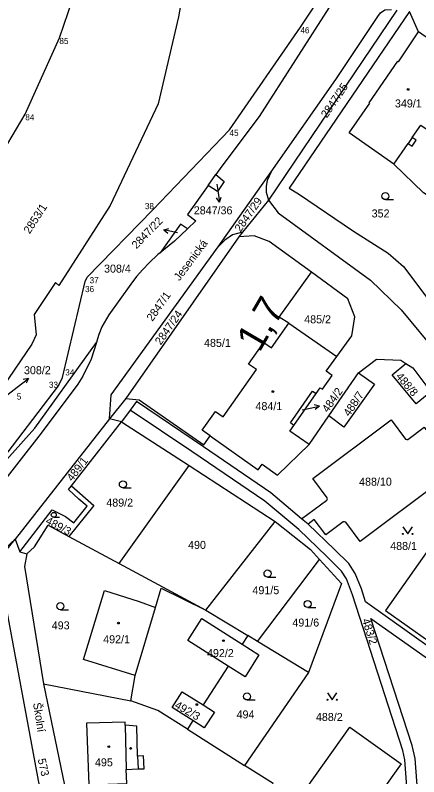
# Model space of a CAD drawing. Extents: x -558358 to -557517, y -1073785 to -1073189.
# Drawn here: x -558075.9 to -557990.2, y -1073433.6 to -1073271.9 of the extents above; entities that cross this region are included whole.
import ezdxf

# ---------------------------------------------------------------- set-up
doc = ezdxf.new("R2010")
doc.units = 0
for name, color, linetype in [('Hranice parcel', 7, 'Continuous'), ('Návěst místo trati', 7, 'Continuous'), ('Parcelní čísla', 7, 'Continuous'), ('Pop  PČ popisy', 7, 'Continuous'), ('Svazek obcí údolí Desné', 7, 'Continuous'), ('Vnitřní kresba', 7, 'Continuous'), ('Vrstva 60', 7, 'Continuous'), ('Značky budov', 7, 'Continuous'), ('Značky kultur', 7, 'Continuous')]:
    doc.layers.add(name, color=color, linetype=linetype)

msp = doc.modelspace()

# ---------------------------------------------------------------- linework, layer by layer
at = {"layer": 'Hranice parcel'}
for p, q in [((-557994.86, -1073270.9), (-558022.09, -1073311.21)), ((-557990.25, -1073275.48), (-557992.18, -1073271.14)), ((-558032.81, -1073321.13), (-558021.55, -1073305.19)), ((-558034.93, -1073308.06), (-558033.31, -1073305.78)), ((-558033.31, -1073305.78), (-558031.49, -1073307.27)), ((-558032.97, -1073309.39), (-558034.93, -1073308.06)), ((-558031.49, -1073307.27), (-558032.97, -1073309.39)), ((-558022.59, -1073309.53), (-558022.09, -1073311.21)), ((-558022.09, -1073311.21), (-558027.65, -1073318.03)), ((-558037.52, -1073315.57), (-558039.34, -1073317.31)), ((-558039.34, -1073317.31), (-558042.1, -1073319.93)), ((-558027.65, -1073318.03), (-558029.72, -1073318.58)), ((-558027.65, -1073318.03), (-558028.41, -1073318.97)), ((-558028.41, -1073318.97), (-558052.39, -1073353.27)), ((-558042.1, -1073319.93), (-558045.13, -1073322.4)), ((-558045.13, -1073322.4), (-558045.59, -1073322.77)), ((-558017.77, -1073337.32), (-558007.59, -1073344.4)), ((-558058.43, -1073340.61), (-558058.64, -1073341.4)), ((-558058.64, -1073341.4), (-558059.76, -1073344.95)), ((-558009.3, -1073357), (-558003.01, -1073347.89)), ((-558003.01, -1073347.89), (-557999.59, -1073350.23)), ((-557999.59, -1073350.23), (-558006.08, -1073359.37)), ((-558016.74, -1073359.04), (-558011.99, -1073352.26)), ((-558055.85, -1073357.6), (-558055.56, -1073352.56)), ((-558052.39, -1073353.27), (-558055.85, -1073357.6)), ((-558051.46, -1073355.75), (-558053.32, -1073358.25)), ((-558013.44, -1073363.06), (-558009.3, -1073357)), ((-558006.08, -1073359.37), (-558009.3, -1073357)), ((-558055.85, -1073357.6), (-558075.89, -1073383.19)), ((-558063.99, -1073371.84), (-558053.32, -1073358.25)), ((-558053.32, -1073358.25), (-558055.85, -1073357.6)), ((-558053.32, -1073358.25), (-558038.99, -1073367.55)), ((-558053.86, -1073388.3), (-558038.99, -1073367.55)), ((-558038.99, -1073367.55), (-558020.67, -1073379.44)), ((-558035.4, -1073398.23), (-558020.67, -1073379.44)), ((-558075.89, -1073383.19), (-558086.19, -1073392.25)), ((-558081, -1073389.4), (-558075.89, -1073383.19)), ((-558075.89, -1073383.19), (-558074.9, -1073385.82)), ((-558064.49, -1073382.58), (-558053.86, -1073388.3)), ((-558074.9, -1073385.82), (-558073.48, -1073386.28)), ((-558024.42, -1073404.91), (-558011.29, -1073387.48)), ((-558053.86, -1073388.3), (-558035.4, -1073398.23)), ((-558068.26, -1073448.76), (-558079.07, -1073390.9)), ((-558035.4, -1073398.23), (-558026.52, -1073403.63)), ((-558039.27, -1073404.7), (-558036.29, -1073400)), ((-558036.29, -1073400), (-558027.69, -1073405.45)), ((-558026.52, -1073403.63), (-558027.69, -1073405.45)), ((-558024.42, -1073404.91), (-558026.52, -1073403.63)), ((-558030.69, -1073410.09), (-558039.27, -1073404.7)), ((-558027.69, -1073405.45), (-558024.15, -1073407.69)), ((-558013.61, -1073411.49), (-558024.42, -1073404.91)), ((-558024.15, -1073407.69), (-558027.08, -1073412.36)), ((-558030.69, -1073410.09), (-558036.02, -1073418.35)), ((-558027.08, -1073412.36), (-558030.69, -1073410.09)), ((-558013.61, -1073411.49), (-558027.22, -1073431.17)), ((-558069.9, -1073413.89), (-558063.79, -1073443.12)), ((-558069.9, -1073413.89), (-558051.38, -1073417.49)), ((-558042.56, -1073418.87), (-558040.48, -1073415.56)), ((-558040.48, -1073415.56), (-558036.02, -1073418.35)), ((-558036.02, -1073418.35), (-558033.6, -1073419.86)), ((-558038.16, -1073421.67), (-558042.56, -1073418.87)), ((-558033.6, -1073419.86), (-558035.74, -1073423.21)), ((-558038.16, -1073421.67), (-558039.34, -1073423.5)), ((-558035.74, -1073423.21), (-558038.16, -1073421.67)), ((-558039.34, -1073423.5), (-558027.22, -1073431.17))]:
    msp.add_line(p, q, dxfattribs=at)
for points in [[(-557998.11, -1073217.81), (-557996.7, -1073222.28), (-557998.38, -1073242.39), (-558002.78, -1073257.43), (-558008.62, -1073269.37), (-558024.06, -1073293.44), (-558032.02, -1073303.96), (-558033.31, -1073305.78)], [(-558021.55, -1073305.19), (-558007.79, -1073285.56), (-557998.91, -1073272.25), (-557998.29, -1073271.45), (-557997.41, -1073270.82), (-557995.96, -1073270.7)], [(-557992.18, -1073271.14), (-558017.7, -1073308.66), (-558015.75, -1073309.85), (-558004.08, -1073317.8), (-557996.67, -1073322.48), (-557993.43, -1073325.31), (-557988.49, -1073331.84)], [(-557995.47, -1073303.55), (-558004.99, -1073296.92), (-558000.61, -1073290.62), (-558000.75, -1073290.52), (-557994.62, -1073281.73), (-557994.47, -1073281.84), (-557990.25, -1073275.48)], [(-557995.47, -1073303.55), (-557992.42, -1073299.14), (-557991.6, -1073299.71), (-557990.74, -1073298.46), (-557991.57, -1073297.9), (-557989.74, -1073295.26), (-557987.45, -1073296.82), (-557987.09, -1073296.7), (-557984.08, -1073292.32), (-557984.13, -1073291.92), (-557983.12, -1073290.42), (-557984.28, -1073289.64), (-557980.42, -1073284.02), (-557980.45, -1073282.32), (-557980.68, -1073282.11), (-557990.25, -1073275.48)], [(-557977.43, -1073317.43), (-557989.2, -1073309.62), (-557995.47, -1073303.55)], [(-558021.55, -1073305.19), (-558022.41, -1073307.04), (-558022.62, -1073308.24), (-558022.59, -1073309.53)], [(-558034.93, -1073308.06), (-558039.34, -1073314.26), (-558037.52, -1073315.57)], [(-558022.09, -1073311.21), (-558020.08, -1073313.87), (-558000.41, -1073328.2), (-557993.92, -1073334.5), (-557986.04, -1073343.93), (-557967.1, -1073369.2), (-557918.24, -1073434.51), (-557914.64, -1073436.24), (-557909.55, -1073436.22), (-557905.05, -1073434.1), (-557902.57, -1073430.65), (-557891.22, -1073414.37), (-557877.97, -1073395.43)], [(-558039.34, -1073317.31), (-558040.78, -1073316.28), (-558045.13, -1073322.4)], [(-558029.72, -1073318.58), (-558031.41, -1073319.68), (-558032.81, -1073321.13)], [(-558012.98, -1073326.49), (-558021.93, -1073320.01), (-558025.13, -1073318.78), (-558028.41, -1073318.97)], [(-558055.56, -1073352.56), (-558041.67, -1073333.36), (-558032.81, -1073321.13)], [(-558045.59, -1073322.77), (-558047.44, -1073324.48), (-558048.82, -1073325.91), (-558050.13, -1073327.44), (-558051.32, -1073329.04), (-558056.02, -1073335.51), (-558057.5, -1073338.08), (-558058.16, -1073339.69), (-558058.43, -1073340.61)], [(-558017.77, -1073337.32), (-558019.82, -1073336.05), (-558012.98, -1073326.49)], [(-558007.59, -1073344.4), (-558004.4, -1073339.98), (-558003.75, -1073335.95), (-558005.22, -1073332.12), (-558012.98, -1073326.49)], [(-558034.47, -1073361.24), (-558036.19, -1073360.05), (-558033.38, -1073356.04), (-558031.73, -1073357.2), (-558024.67, -1073347.17), (-558026.34, -1073346.01), (-558023.11, -1073341.4), (-558021.44, -1073342.56), (-558017.77, -1073337.32)], [(-558083.8, -1073372.96), (-558071.77, -1073359.59), (-558059.92, -1073343.2), (-558058.64, -1073341.4)], [(-558011.99, -1073352.26), (-558011.14, -1073351.05), (-558010.65, -1073351.33), (-558008.6, -1073348.45), (-558009.82, -1073347.53), (-558007.59, -1073344.4)], [(-558059.76, -1073344.95), (-558061.55, -1073348.53), (-558062.6, -1073350.23), (-558070.37, -1073360.66), (-558089.91, -1073385.65), (-558114.04, -1073415.6), (-558119.93, -1073422.75), (-558120.74, -1073423.38), (-558121.71, -1073423.79), (-558122.74, -1073423.86)], [(-558003.01, -1073347.89), (-557999.15, -1073344.94), (-557994.02, -1073345.2), (-557992.92, -1073345.89)], [(-557987.64, -1073351.9), (-557990.77, -1073354.47), (-557995.82, -1073348.28), (-557992.92, -1073345.89)], [(-557992.92, -1073345.89), (-557991.47, -1073346.8), (-557987.64, -1073351.9)], [(-558016.74, -1073359.04), (-558017.42, -1073358.44), (-558012.76, -1073351.73), (-558011.99, -1073352.26)], [(-558052.39, -1073353.27), (-558049.55, -1073353.62), (-558035.82, -1073363.11), (-558034.47, -1073361.24)], [(-558015.07, -1073378.83), (-558021.62, -1073373.3), (-558035.88, -1073363.58), (-558050.18, -1073353.97), (-558051.46, -1073355.75)], [(-557997.16, -1073446.28), (-557996.18, -1073446.14), (-557992.37, -1073440.37), (-557993.13, -1073429.99), (-557993.58, -1073428.02), (-558004.25, -1073395), (-558005.55, -1073391.58), (-558006.57, -1073389.94), (-558009.69, -1073386.81), (-558015.69, -1073381.13), (-558022.86, -1073375.1), (-558038.38, -1073364.54), (-558051.46, -1073355.75)], [(-558015.07, -1073378.83), (-558009.7, -1073374.87), (-558009.55, -1073374.62), (-558009.63, -1073374.36), (-558012.72, -1073370.26), (-557996.07, -1073357.8), (-557992.97, -1073361.92), (-557992.74, -1073362.04), (-557992.48, -1073361.98), (-557989.05, -1073359.38), (-557985.61, -1073364.04), (-557988.36, -1073366.15), (-557988.52, -1073366.38), (-557988.48, -1073366.66), (-557985.4, -1073370.76), (-558002.63, -1073383.68), (-558005.71, -1073379.56), (-558005.98, -1073379.48), (-558006.26, -1073379.51), (-558009.96, -1073382.24), (-558012.37, -1073378.99), (-558013.71, -1073380.01)], [(-558013.44, -1073363.06), (-558017.55, -1073360.24), (-558016.74, -1073359.04)], [(-558034.47, -1073361.24), (-558024.32, -1073368.43), (-558023.47, -1073367.24), (-558020.17, -1073369.56), (-558013.44, -1073363.06)], [(-558074.9, -1073385.82), (-558068.06, -1073376.95), (-558065.25, -1073378.32), (-558063.46, -1073379.72), (-558060.6, -1073376.18), (-558062.42, -1073374.7), (-558064.61, -1073372.63), (-558063.99, -1073371.84)], [(-558063.99, -1073371.84), (-558059.19, -1073376.03), (-558064.49, -1073382.58)], [(-557973.25, -1073383.95), (-557982.53, -1073377.43), (-557997.25, -1073398.28), (-557988.03, -1073404.82), (-557981.86, -1073396.11), (-557980.74, -1073396.9), (-557978.29, -1073393.44), (-557979.41, -1073392.65), (-557973.25, -1073383.95)], [(-558020.67, -1073379.44), (-558013.21, -1073385.39), (-558011.29, -1073387.48)], [(-558013.71, -1073380.01), (-558014.05, -1073379.69), (-558015.07, -1073378.83)], [(-558073.48, -1073386.28), (-558071.82, -1073384.76), (-558068.89, -1073380.22), (-558064.49, -1073382.58)], [(-557986.61, -1073406.29), (-557987.5, -1073406.44), (-558001.47, -1073396.48), (-558002.38, -1073393.7), (-558003.7, -1073390.42), (-558005.05, -1073388.34), (-558008.08, -1073385.35), (-558013.71, -1073380.01)], [(-558073.48, -1073386.28), (-558073.96, -1073388.93), (-558069.9, -1073413.89)], [(-558011.29, -1073387.48), (-558006.6, -1073392.58), (-558013.61, -1073411.49)], [(-558051.38, -1073417.49), (-558050.42, -1073412.09), (-558061.44, -1073408.67), (-558056.95, -1073394.08), (-558049.56, -1073396.36), (-558046.09, -1073397.7), (-558044.91, -1073393.54), (-558035.4, -1073398.23)], [(-557990.11, -1073441.11), (-557990.95, -1073429.72), (-557991.6, -1073426.99), (-558000.34, -1073399.97), (-557986.42, -1073409.86), (-557979.13, -1073399.38), (-557977.23, -1073400.7), (-557975.75, -1073398.59), (-557966.19, -1073404.96)], [(-558039.34, -1073423.5), (-558045.61, -1073419.54), (-558051.38, -1073417.49)], [(-558049.8, -1073431.93), (-558048.54, -1073431.88), (-558048.64, -1073429.15), (-558049.91, -1073429.2), (-558050.08, -1073422.86), (-558052.56, -1073422.66), (-558052.57, -1073422.02), (-558060.76, -1073422.24), (-558060.26, -1073435.32), (-558052.21, -1073435.02), (-558052.32, -1073432.02), (-558049.8, -1073431.93)], [(-558023.22, -1073448.98), (-558004.82, -1073423.06), (-557993.94, -1073430.83), (-558002.36, -1073442.69), (-558001.05, -1073443.62)], [(-558024.27, -1073448.53), (-558022.77, -1073438.58), (-558021.1, -1073435.02), (-558027.22, -1073431.17)]]:
    msp.add_lwpolyline(points, dxfattribs=at)
at = {"layer": 'Pop  PČ popisy'}
for p, q in [((-558033.09, -1073307.84), (-558032.96, -1073308.65)), ((-558032.96, -1073308.65), (-558032.49, -1073311.61)), ((-558032.49, -1073311.61), (-558033.14, -1073310.7)), ((-558032.49, -1073311.61), (-558032.15, -1073310.55)), ((-558044.37, -1073317.47), (-558043.29, -1073317.2)), ((-558041.45, -1073318.14), (-558044.37, -1073317.47)), ((-558044.37, -1073317.47), (-558043.51, -1073318.18)), ((-558075.47, -1073350.88), (-558073.1, -1073349.03)), ((-558073.1, -1073349.03), (-558074.2, -1073349.25)), ((-558073.1, -1073349.03), (-558073.59, -1073350.04)), ((-558078.72, -1073353.4), (-558075.47, -1073350.88)), ((-558014.95, -1073355.7), (-558014.23, -1073355.56)), ((-558014.23, -1073355.56), (-558011.3, -1073354.94)), ((-558011.3, -1073354.94), (-558012.38, -1073354.65)), ((-558011.3, -1073354.94), (-558012.17, -1073355.63))]:
    msp.add_line(p, q, dxfattribs=at)
at = {"layer": 'Svazek obcí údolí Desné'}
msp.add_line((-558083.8, -1073372.96), (-558066.74, -1073350.64), dxfattribs=at)
for points in [[(-558082.18, -1073306.93), (-558073.77, -1073292.96), (-558066.53, -1073276.76), (-558060.05, -1073257.85), (-558056.4, -1073244.89), (-558045.6, -1073201.5), (-558043.07, -1073189.63)], [(-558025.59, -1073189.61), (-558032.09, -1073212.63), (-558035.15, -1073249.33), (-558039.97, -1073265.01), (-558041.24, -1073272.26), (-558045.55, -1073290.79), (-558055.77, -1073312.33), (-558066.64, -1073329.29), (-558067.37, -1073328.67), (-558071.91, -1073335.47), (-558071.45, -1073339.78), (-558072.38, -1073341.74), (-558078.52, -1073350.81)], [(-558066.74, -1073350.64), (-558065.9, -1073348.86), (-558061.08, -1073328.44), (-558060.65, -1073327.54), (-558046.7, -1073313.29), (-558030.4, -1073296.27), (-558015.33, -1073274.48), (-558010.02, -1073266.4), (-558006.82, -1073259.79), (-558003.58, -1073251.39), (-558001.93, -1073245.63), (-558000.3, -1073233.47), (-558000.14, -1073230.76), (-558000.21, -1073228.76), (-558000.67, -1073225.31), (-558001.93, -1073222.03), (-558003.18, -1073219.55), (-558003.41, -1073218.32), (-558003.28, -1073217.31), (-558002.8, -1073216.38), (-558000.9, -1073214.81), (-557999.34, -1073213.91), (-558005.3, -1073194.99), (-558007.29, -1073189.83)]]:
    msp.add_lwpolyline(points, dxfattribs=at)
at = {"layer": 'Vnitřní kresba'}
for p, q in [((-557991.57, -1073297.9), (-557992.42, -1073299.14)), ((-558050.42, -1073412.09), (-558046.09, -1073397.7)), ((-558052.56, -1073422.66), (-558052.32, -1073432.02)), ((-558049.91, -1073429.2), (-558049.8, -1073431.93))]:
    msp.add_line(p, q, dxfattribs=at)
at = {"layer": 'Vrstva 60'}
for p, q in [((-558015.33, -1073274.48), (-558015.33, -1073274.48)), ((-558066.53, -1073276.76), (-558066.53, -1073276.76)), ((-558073.77, -1073292.96), (-558073.77, -1073292.96)), ((-558030.4, -1073296.27), (-558030.4, -1073296.27)), ((-558046.7, -1073313.29), (-558046.7, -1073313.29)), ((-558060.65, -1073327.54), (-558060.65, -1073327.54)), ((-558061.08, -1073328.44), (-558061.08, -1073328.44)), ((-558065.9, -1073348.86), (-558065.9, -1073348.86)), ((-558066.74, -1073350.64), (-558066.74, -1073350.64))]:
    msp.add_line(p, q, dxfattribs=at)
at = {"layer": 'Značky budov'}
for centre in [(-557992.44, -1073287.7), (-558021.18, -1073351.82), (-558053.98, -1073400.98), (-558031.67, -1073404.71), (-558037.33, -1073418.27), (-558056.04, -1073427.22), (-558051.4, -1073427.58)]:
    msp.add_circle(centre, 0.175, dxfattribs=at)
at = {"layer": 'Značky kultur'}
for p, q in [((-557997.27, -1073311.09), (-557995.52, -1073311.09)), ((-558053.04, -1073372.28), (-558051.29, -1073372.28)), ((-558067.72, -1073378.52), (-558066.5, -1073378.52)), ((-558022.31, -1073391.2), (-558020.56, -1073391.2)), ((-558013.78, -1073397.68), (-558012.03, -1073397.68)), ((-558066.32, -1073398.13), (-558064.57, -1073398.13)), ((-558026.66, -1073417.3), (-558024.91, -1073417.3))]:
    msp.add_line(p, q, dxfattribs=at)
for points in [[(-557993.54, -1073380.54), (-557992.54, -1073382.04), (-557991.54, -1073380.54)], [(-558009.6, -1073415.75), (-558008.6, -1073417.25), (-558007.6, -1073415.75)]]:
    msp.add_lwpolyline(points, dxfattribs=at)
for centre, radius in [((-557997.27, -1073310.34), 0.75), ((-558053.04, -1073371.53), 0.75), ((-558067.72, -1073378), 0.525), ((-557993.54, -1073382.04), 0.1), ((-557991.54, -1073382.04), 0.1), ((-558022.31, -1073390.45), 0.75), ((-558066.32, -1073397.38), 0.75), ((-558013.78, -1073396.93), 0.75), ((-558026.66, -1073416.55), 0.75), ((-558009.6, -1073417.25), 0.1), ((-558007.6, -1073417.25), 0.1)]:
    msp.add_circle(centre, radius, dxfattribs=at)

# ---------------------------------------------------------------- texts
at = {"layer": 'Návěst místo trati'}
msp.add_text('1,7', height=6, rotation=59.7051, dxfattribs=at).set_placement((-558024.05, -1073343.72))
at = {"layer": 'Parcelní čísla'}
for s, rotation, p in [('2847/25', 56, (-558009.7, -1073293.88)), ('2847/29', 55, (-558028.06, -1073318.09)), ('2853/1', 57, (-558072.84, -1073318.48)), ('2847/22', 46, (-558050.14, -1073321.67)), ('2847/1', 55, (-558046.76, -1073337.06)), ('2847/24', 55, (-558045, -1073342.08)), ('488/8', 310, (-557995.15, -1073348.66)), ('484/2', 55, (-558009.5, -1073356.42)), ('488/7', 56, (-558004.94, -1073357.25)), ('489/1', 52, (-558063.81, -1073371.04)), ('489/3', 332, (-558069.62, -1073379.77)), ('483/2', 288, (-558002.27, -1073400.31)), ('492/3', 330, (-558042.19, -1073418.87)), ('573', 283, (-558071.15, -1073429.91))]:
    msp.add_text(s, height=1.7, rotation=rotation, dxfattribs=at).set_placement(p)
for s, p in [('349/1', (-557995.24, -1073291.52)), ('2847/36', (-558037.98, -1073314.21)), ('352', (-558000.19, -1073314.87)), ('308/4', (-558057.04, -1073326.58)), ('485/2', (-558014.52, -1073337.34)), ('485/1', (-558035.8, -1073342.35)), ('308/2', (-558074.05, -1073348.15)), ('484/1', (-558024.87, -1073355.77)), ('488/10', (-558002.86, -1073371.81)), ('489/2', (-558056.56, -1073376.25)), ('490', (-558039.19, -1073385.23)), ('488/1', (-557996.25, -1073385.45)), ('491/5', (-558025.51, -1073394.84)), ('493', (-558068.15, -1073402.31)), ('491/6', (-558017.03, -1073401.71)), ('492/1', (-558057.22, -1073405.26)), ('492/2', (-558035.17, -1073408.19)), ('494', (-558028.89, -1073421.21)), ('488/2', (-558012.03, -1073421.76)), ('495', (-558058.97, -1073431.38))]:
    msp.add_text(s, height=1.7, dxfattribs=at).set_placement(p)
at = {"layer": 'Pop  PČ popisy'}
for s, rotation, p in [('Jesenická', 53, (-558041.01, -1073328.46)), ('Školní', 279, (-558072.13, -1073417.99))]:
    msp.add_text(s, height=1.7, rotation=rotation, dxfattribs=at).set_placement(p)
at = {"layer": 'Vrstva 60'}
for s, p in [('46', (-558015.33, -1073275.78)), ('85', (-558066.53, -1073278.06)), ('84', (-558073.77, -1073294.26)), ('45', (-558030.4, -1073297.57)), ('38', (-558048.37, -1073313.11)), ('37', (-558060.12, -1073328.84)), ('36', (-558061.08, -1073330.72)), ('34', (-558065.29, -1073348.41)), ('33', (-558068.75, -1073351.04)), ('5', (-558075.59, -1073353.53))]:
    msp.add_text(s, height=1.3, dxfattribs=at).set_placement(p)

doc.saveas('drawing.dxf')
